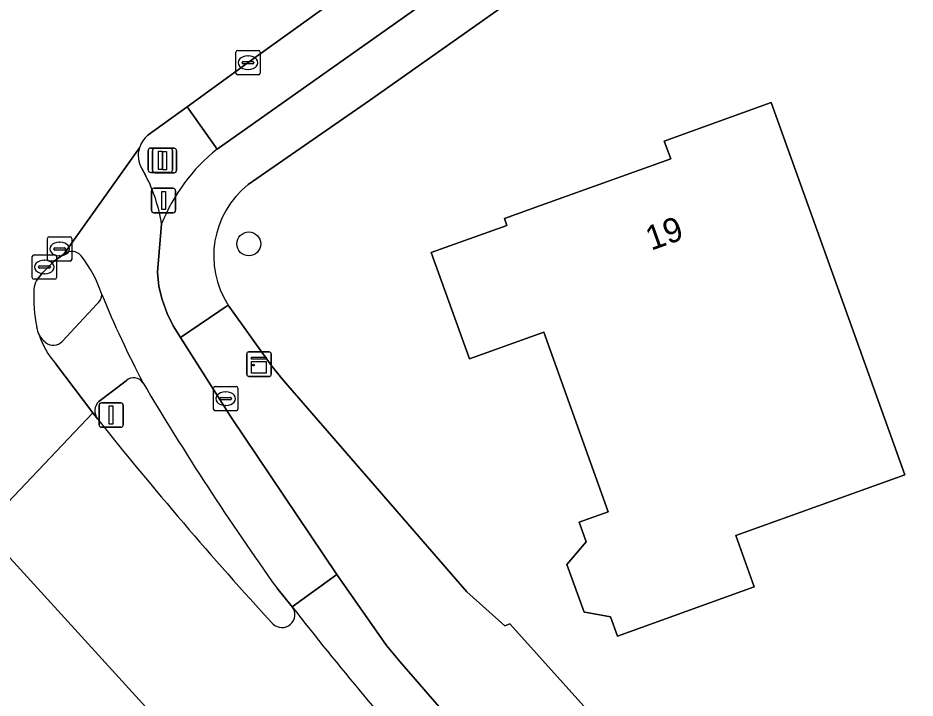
# Model space of a CAD drawing. Extents: x 161087 to 161926, y 382572 to 383873.
# Drawn here: x 161565.04 to 161601.79, y 382729.82 to 382757.68 of the extents above; entities that cross this region are included whole.
import ezdxf

# ---------------------------------------------------------------- set-up
doc = ezdxf.new("R2010")
doc.units = 0
for name, color, linetype in [('IMGEO_Berm_groen', 7, 'Continuous'), ('IMGEO_Boom', 7, 'Continuous'), ('IMGEO_Drukknoppaal', 7, 'Continuous'), ('IMGEO_Erf', 7, 'Continuous'), ('IMGEO_Fietspad_gesloten', 7, 'Continuous'), ('IMGEO_Kast', 7, 'Continuous'), ('IMGEO_Kolk', 7, 'Continuous'), ('IMGEO_Lichtmast', 7, 'Continuous'), ('IMGEO_Pand', 7, 'Continuous'), ('IMGEO_Pand_nummerreeks', 7, 'Continuous'), ('IMGEO_Rijbaan_lokaal_gesloten', 7, 'Continuous'), ('IMGEO_Rioolput', 7, 'Continuous'), ('IMGEO_Verkeerseiland_groen', 7, 'Continuous'), ('IMGEO_Verkeerseiland_open', 7, 'Continuous'), ('IMGEO_Verkeersregelinstallatiepaal', 7, 'Continuous'), ('IMGEO_Voetpad_open', 7, 'Continuous')]:
    doc.layers.add(name, color=color, linetype=linetype)

msp = doc.modelspace()

# ---------------------------------------------------------------- linework, layer by layer
at = {"layer": 'IMGEO_Berm_groen'}
msp.add_lwpolyline([(161583.108, 382762.07), (161574.467, 382755.852), (161571.968, 382754.036), (161573.199, 382752.31), (161584.417, 382760.236)], close=True, dxfattribs=at)
at = {"layer": 'IMGEO_Boom'}
msp.add_circle((161574.495, 382748.426), 0.489, dxfattribs=at)
at = {"layer": 'IMGEO_Drukknoppaal'}
for p, q in [((161570.509, 382749.804), (161570.509, 382750.604)), ((161570.509, 382750.604), (161570.509, 382749.804)), ((161570.609, 382750.704), (161571.399, 382750.704)), ((161571.399, 382750.704), (161570.609, 382750.704)), ((161571.499, 382750.604), (161571.499, 382749.804)), ((161571.499, 382749.804), (161571.499, 382750.604)), ((161571.399, 382749.704), (161570.609, 382749.704)), ((161570.609, 382749.704), (161571.399, 382749.704))]:
    msp.add_line(p, q, dxfattribs=at)
msp.add_lwpolyline([(161570.929, 382750.579), (161571.079, 382750.579), (161571.079, 382749.829), (161570.929, 382749.829), (161570.929, 382750.579)], dxfattribs=at)
for centre, start, end in [((161570.609, 382750.604), 90, 180), ((161570.609, 382750.604), 90, 180), ((161571.399, 382750.604), 0, 90), ((161571.399, 382750.604), 360, 90), ((161570.609, 382749.804), 180, 270), ((161570.609, 382749.804), 180, 270), ((161571.399, 382749.804), 270, 0), ((161571.399, 382749.804), 270, 0)]:
    msp.add_arc(centre, 0.1, start, end, dxfattribs=at)
at = {"layer": 'IMGEO_Erf'}
for points in [[(161585.099, 382758.295), (161583.93, 382757.469), (161579.443, 382754.299), (161574.477, 382750.86)], [(161573.649, 382745.916), (161575.439, 382743.417), (161575.924, 382742.835), (161583.433, 382734.169), (161584.982, 382732.778), (161585.192, 382732.858), (161589.562, 382727.999), (161609.424, 382705.975), (161609.305, 382705.895), (161625.238, 382688.024), (161643.165, 382669.38), (161647.852, 382664.262), (161649.374, 382662.6), (161650.008, 382663.023), (161699.247, 382695.877)]]:
    msp.add_lwpolyline(points, dxfattribs=at)
msp.add_lwpolyline([(161594.454, 382736.477), (161595.209, 382734.375), (161589.598, 382732.359), (161589.314, 382733.148), (161588.344, 382733.323), (161588.234, 382733.343), (161587.533, 382735.297), (161588.317, 382736.223), (161588.03, 382737.021), (161589.223, 382737.449), (161586.579, 382744.808), (161583.533, 382743.714), (161581.968, 382748.071), (161585.069, 382749.185), (161584.968, 382749.468), (161586.449, 382750), (161589.573, 382751.122), (161591.782, 382751.916), (161591.521, 382752.641), (161595.899, 382754.214), (161597.414, 382750), (161597.59, 382749.509), (161601.378, 382738.964)], close=True, dxfattribs=at)
msp.add_arc((161576.794, 382747.931), 3.735, 128.3379, 212.6472, dxfattribs=at)
at = {"layer": 'IMGEO_Fietspad_gesloten'}
for points in [[(161570.013, 382752.358), (161566.925, 382748.01)], [(161570.28, 382751.211), (161570.108, 382751.515)], [(161571.694, 382744.598), (161571.391, 382745.076), (161571.156, 382745.58), (161570.946, 382746.155), (161570.804, 382746.685), (161570.753, 382747.268), (161570.926, 382749.243)], [(161575.639, 382734.33), (161576.275, 382733.561), (161578.104, 382734.877), (161573.766, 382741.336), (161571.694, 382744.598)]]:
    msp.add_lwpolyline(points, dxfattribs=at)
for centre, radius, start, end in [((161571.032, 382752.046), 1.066, 162.985, 209.8744), ((161564.445, 382748.205), 6.564, 9.0944, 27.2506), ((161567.236, 382747.617), 0.502, 94.1565, 128.3646), ((161567.236, 382747.608), 0.511, 39.8763, 94.05), ((161563.826, 382744.884), 4.875, 17.6251, 38.7462), ((161608.75, 382762.934), 43.555, 202.3667, 207.6464), ((161673.047, 382803.798), 119.642, 210.69545, 215.49516)]:
    msp.add_arc(centre, radius, start, end, dxfattribs=at)
at = {"layer": 'IMGEO_Kast'}
for p, q in [((161574.414, 382743.075), (161574.414, 382743.916)), ((161574.414, 382743.916), (161574.414, 382743.075)), ((161574.489, 382744), (161575.33, 382744)), ((161575.33, 382744), (161574.489, 382744)), ((161575.414, 382743.925), (161575.414, 382743.084)), ((161575.414, 382743.084), (161575.414, 382743.925)), ((161575.339, 382743), (161574.498, 382743)), ((161574.498, 382743), (161575.339, 382743))]:
    msp.add_line(p, q, dxfattribs=at)
for points in [[(161574.609, 382743.79), (161575.209, 382743.79), (161575.209, 382743.705), (161574.609, 382743.705), (161574.609, 382743.79)], [(161574.609, 382743.615), (161575.209, 382743.615), (161575.209, 382743.126), (161574.609, 382743.126), (161574.609, 382743.615)]]:
    msp.add_lwpolyline(points, dxfattribs=at)
msp.add_circle((161574.693, 382743.464), 0.0377, dxfattribs=at)
for centre, start, end in [((161574.492, 382743.922), 92.4484, 184.2845), ((161574.492, 382743.922), 92.4484, 184.2845), ((161575.336, 382743.922), 2.4484, 94.2845), ((161575.336, 382743.922), 2.4484, 94.2845), ((161574.492, 382743.078), 182.4484, 274.2845), ((161574.492, 382743.078), 182.4484, 274.2845), ((161575.336, 382743.078), 272.4484, 4.2845), ((161575.336, 382743.078), 272.4484, 4.2845)]:
    msp.add_arc(centre, 0.0779, start, end, dxfattribs=at)
at = {"layer": 'IMGEO_Kolk'}
for p, q in [((161573.966, 382755.426), (161573.966, 382756.278)), ((161574.041, 382756.352), (161574.893, 382756.352)), ((161574.967, 382756.278), (161574.967, 382755.426)), ((161574.225, 382755.846), (161574.225, 382755.858)), ((161574.268, 382755.895), (161574.666, 382755.895)), ((161574.454, 382756.132), (161574.479, 382756.132)), ((161574.709, 382755.858), (161574.709, 382755.846)), ((161574.663, 382755.809), (161574.265, 382755.809)), ((161574.477, 382755.572), (161574.452, 382755.572)), ((161574.893, 382755.352), (161574.041, 382755.352)), ((161565.623, 382747.052), (161565.623, 382747.904)), ((161565.698, 382747.978), (161566.55, 382747.978)), ((161566.624, 382747.904), (161566.624, 382747.052)), ((161565.882, 382747.472), (161565.882, 382747.484)), ((161566.32, 382747.435), (161565.922, 382747.435)), ((161565.925, 382747.521), (161566.323, 382747.521)), ((161566.111, 382747.758), (161566.136, 382747.758)), ((161566.366, 382747.484), (161566.366, 382747.472)), ((161566.134, 382747.198), (161566.109, 382747.198)), ((161566.55, 382746.978), (161565.698, 382746.978)), ((161573.048, 382741.661), (161573.048, 382742.513)), ((161573.123, 382742.587), (161573.975, 382742.587)), ((161573.536, 382742.367), (161573.561, 382742.367)), ((161574.049, 382742.513), (161574.049, 382741.661)), ((161573.307, 382742.081), (161573.307, 382742.093)), ((161573.745, 382742.044), (161573.347, 382742.044)), ((161573.35, 382742.13), (161573.748, 382742.13)), ((161573.791, 382742.093), (161573.791, 382742.081)), ((161573.975, 382741.587), (161573.123, 382741.587)), ((161573.559, 382741.807), (161573.534, 382741.807))]:
    msp.add_line(p, q, dxfattribs=at)
for points in [[(161573.966, 382755.426), (161573.966, 382756.278)], [(161574.041, 382756.352), (161574.893, 382756.352)], [(161574.967, 382756.278), (161574.967, 382755.426)], [(161574.893, 382755.352), (161574.041, 382755.352)], [(161565.623, 382747.052), (161565.623, 382747.904)], [(161565.698, 382747.978), (161566.55, 382747.978)], [(161566.624, 382747.904), (161566.624, 382747.052)], [(161566.55, 382746.978), (161565.698, 382746.978)], [(161573.048, 382741.661), (161573.048, 382742.513)], [(161573.123, 382742.587), (161573.975, 382742.587)], [(161574.049, 382742.513), (161574.049, 382741.661)], [(161573.975, 382741.587), (161573.123, 382741.587)]]:
    msp.add_lwpolyline(points, dxfattribs=at)
for centre, radius, start, end in [((161574.043, 382756.276), 0.0765, 91.552, 178.448), ((161574.043, 382756.276), 0.0765, 91.552, 178.448), ((161574.891, 382756.276), 0.0765, 1.552, 88.448), ((161574.891, 382756.276), 0.0765, 1.552, 88.448), ((161574.265, 382755.855), 0.0403, 85.8775, 175.7526), ((161574.67, 382755.857), 0.0386, 1.7309, 96.639), ((161574.262, 382755.845), 0.0366, 178.938, 274.7102), ((161574.666, 382755.852), 0.043, 264.8664, 352.4533), ((161574.043, 382755.428), 0.0765, 181.552, 268.448), ((161574.043, 382755.428), 0.0765, 181.552, 268.448), ((161574.891, 382755.428), 0.0765, 271.552, 358.448), ((161574.891, 382755.428), 0.0765, 271.552, 358.448), ((161565.7, 382747.902), 0.0765, 91.552, 178.448), ((161565.7, 382747.902), 0.0765, 91.552, 178.448), ((161566.548, 382747.902), 0.0765, 1.552, 88.448), ((161566.548, 382747.902), 0.0765, 1.552, 88.448), ((161565.922, 382747.481), 0.0403, 85.8775, 175.7526), ((161565.919, 382747.471), 0.0366, 178.938, 274.7102), ((161566.323, 382747.478), 0.043, 264.8664, 352.4533), ((161566.327, 382747.483), 0.0386, 1.7309, 96.639), ((161565.7, 382747.054), 0.0765, 181.552, 268.448), ((161565.7, 382747.054), 0.0765, 181.552, 268.448), ((161566.548, 382747.054), 0.0765, 271.552, 358.448), ((161566.548, 382747.054), 0.0765, 271.552, 358.448), ((161573.125, 382742.511), 0.0765, 91.552, 178.448), ((161573.125, 382742.511), 0.0765, 91.552, 178.448), ((161573.973, 382742.511), 0.0765, 1.552, 88.448), ((161573.973, 382742.511), 0.0765, 1.552, 88.448), ((161573.347, 382742.09), 0.0403, 85.8775, 175.7526), ((161573.344, 382742.08), 0.0366, 178.938, 274.7102), ((161573.748, 382742.087), 0.043, 264.8664, 352.4533), ((161573.752, 382742.092), 0.0386, 1.7309, 96.639), ((161573.125, 382741.663), 0.0765, 181.552, 268.448), ((161573.125, 382741.663), 0.0765, 181.552, 268.448), ((161573.973, 382741.663), 0.0765, 271.552, 358.448), ((161573.973, 382741.663), 0.0765, 271.552, 358.448)]:
    msp.add_arc(centre, radius, start, end, dxfattribs=at)
for centre, major_axis, ratio, start_param, end_param in [((161574.453, 382755.852), (-0.387, 0.002), 0.722429, 4.712389, 7.853982), ((161574.478, 382755.852), (-0.39, 0.002), 0.717154, 1.570796, 4.712389), ((161566.11, 382747.478), (-0.387, 0.002), 0.722429, 4.712389, 7.853982), ((161566.135, 382747.478), (-0.39, 0.002), 0.717154, 1.570796, 4.712389), ((161573.535, 382742.087), (-0.387, 0.002), 0.722429, 4.712389, 7.853982), ((161573.56, 382742.087), (-0.39, 0.002), 0.717154, 1.570796, 4.712389)]:
    msp.add_ellipse(centre, major_axis=major_axis, ratio=ratio, start_param=start_param, end_param=end_param, dxfattribs=at)
at = {"layer": 'IMGEO_Lichtmast'}
for p, q in [((161570.376, 382751.454), (161570.376, 382752.254)), ((161570.376, 382752.254), (161570.376, 382751.454)), ((161570.476, 382752.354), (161571.266, 382752.354)), ((161571.266, 382752.354), (161570.476, 382752.354)), ((161571.366, 382752.254), (161571.366, 382751.454)), ((161571.366, 382751.454), (161571.366, 382752.254)), ((161571.266, 382751.354), (161570.476, 382751.354)), ((161570.476, 382751.354), (161571.266, 382751.354)), ((161568.462, 382741.914), (161569.252, 382741.914)), ((161569.252, 382741.914), (161568.462, 382741.914)), ((161568.362, 382741.014), (161568.362, 382741.814)), ((161568.362, 382741.814), (161568.362, 382741.014)), ((161569.352, 382741.814), (161569.352, 382741.014)), ((161569.352, 382741.014), (161569.352, 382741.814)), ((161569.252, 382740.914), (161568.462, 382740.914)), ((161568.462, 382740.914), (161569.252, 382740.914))]:
    msp.add_line(p, q, dxfattribs=at)
for points in [[(161570.796, 382752.229), (161570.946, 382752.229), (161570.946, 382751.479), (161570.796, 382751.479), (161570.796, 382752.229)], [(161568.782, 382741.789), (161568.932, 382741.789), (161568.932, 382741.039), (161568.782, 382741.039), (161568.782, 382741.789)]]:
    msp.add_lwpolyline(points, dxfattribs=at)
for centre, start, end in [((161570.476, 382752.254), 90, 180), ((161570.476, 382752.254), 90, 180), ((161571.266, 382752.254), 0, 90), ((161571.266, 382752.254), 360, 90), ((161570.476, 382751.454), 180, 270), ((161570.476, 382751.454), 180, 270), ((161571.266, 382751.454), 270, 0), ((161571.266, 382751.454), 270, 0), ((161568.462, 382741.814), 90, 180), ((161568.462, 382741.814), 90, 180), ((161569.252, 382741.814), 0, 90), ((161569.252, 382741.814), 360, 90), ((161568.462, 382741.014), 180, 270), ((161568.462, 382741.014), 180, 270), ((161569.252, 382741.014), 270, 0), ((161569.252, 382741.014), 270, 0)]:
    msp.add_arc(centre, 0.1, start, end, dxfattribs=at)
at = {"layer": 'IMGEO_Pand'}
msp.add_lwpolyline([(161597.59, 382749.509), (161597.414, 382750), (161595.899, 382754.214), (161591.521, 382752.641), (161591.782, 382751.916), (161589.573, 382751.122), (161586.449, 382750), (161584.968, 382749.468), (161585.069, 382749.185), (161581.968, 382748.071), (161583.533, 382743.714), (161586.579, 382744.808), (161589.223, 382737.449), (161588.03, 382737.021), (161588.317, 382736.223), (161587.533, 382735.297), (161588.234, 382733.343), (161588.344, 382733.323), (161589.314, 382733.148), (161589.598, 382732.359), (161595.209, 382734.375), (161594.454, 382736.477), (161601.378, 382738.964)], close=True, dxfattribs=at)
at = {"layer": 'IMGEO_Rijbaan_lokaal_gesloten'}
for points in [[(161570.366, 382752.877), (161571.968, 382754.036), (161574.467, 382755.852), (161583.108, 382762.07), (161586.012, 382764.231), (161587.661, 382765.339)], [(161565.793, 382746.923), (161566.041, 382747.244), (161566.525, 382747.721), (161566.925, 382748.01), (161570.013, 382752.358)], [(161563.602, 382736.77), (161568.108, 382741.507), (161566.572, 382743.531)], [(161568.297, 382741.258), (161568.108, 382741.507), (161563.602, 382736.77)], [(161563.602, 382736.77), (161592.087, 382705.487), (161622.627, 382671.947), (161661.586, 382630.771), (161701.238, 382588.176), (161728.827, 382571.874), (161779.525, 382578.285), (161779.123, 382582.55), (161766.2, 382581.371), (161761.033, 382580.909)], [(161645.804, 382661.238), (161642.351, 382664.758), (161637.265, 382669.796), (161627.567, 382679.823), (161618.288, 382689.808), (161609.858, 382699.184), (161593.448, 382717.185), (161584.083, 382727.396), (161580.691, 382731.313), (161580.138, 382731.973), (161578.104, 382734.877), (161576.275, 382733.561)]]:
    msp.add_lwpolyline(points, dxfattribs=at)
for centre, radius, start, end in [((161571.026, 382752.049), 1.059, 128.5419, 163.0146), ((161566.711, 382746.478), 1.02, 154.1292, 174.7554), ((161571.424, 382746.189), 5.741, 176.1829, 191.8685), ((161566.749, 382745.15), 0.955, 188.5306, 208.2284), ((161569.149, 382745.77), 3.414, 198.2975, 220.9806), ((161690.519, 382838.569), 156.229, 218.52637, 222.58178), ((161575.853, 382733.24), 0.53, 226.1289, 37.2011), ((161683.305, 382816.893), 135.645, 217.90373, 221.83054), ((161683.305, 382816.893), 135.645, 217.90373, 221.83054)]:
    msp.add_arc(centre, radius, start, end, dxfattribs=at)
at = {"layer": 'IMGEO_Rioolput'}
for p, q in [((161566.245, 382747.793), (161566.245, 382748.645)), ((161566.32, 382748.719), (161567.172, 382748.719)), ((161567.246, 382748.645), (161567.246, 382747.793)), ((161566.504, 382748.213), (161566.504, 382748.225)), ((161566.942, 382748.176), (161566.544, 382748.176)), ((161566.547, 382748.262), (161566.945, 382748.262)), ((161566.733, 382748.499), (161566.758, 382748.499)), ((161566.988, 382748.225), (161566.988, 382748.213)), ((161566.756, 382747.939), (161566.731, 382747.939)), ((161567.172, 382747.719), (161566.32, 382747.719))]:
    msp.add_line(p, q, dxfattribs=at)
for points in [[(161566.245, 382747.793), (161566.245, 382748.645)], [(161566.32, 382748.719), (161567.172, 382748.719)], [(161567.246, 382748.645), (161567.246, 382747.793)], [(161567.172, 382747.719), (161566.32, 382747.719)]]:
    msp.add_lwpolyline(points, dxfattribs=at)
for centre, radius, start, end in [((161566.322, 382748.643), 0.0765, 91.552, 178.448), ((161566.322, 382748.643), 0.0765, 91.552, 178.448), ((161567.17, 382748.643), 0.0765, 1.552, 88.448), ((161567.17, 382748.643), 0.0765, 1.552, 88.448), ((161566.544, 382748.222), 0.0403, 85.8775, 175.7526), ((161566.541, 382748.212), 0.0366, 178.938, 274.7102), ((161566.945, 382748.219), 0.043, 264.8664, 352.4533), ((161566.949, 382748.224), 0.0386, 1.7309, 96.639), ((161566.322, 382747.795), 0.0765, 181.552, 268.448), ((161566.322, 382747.795), 0.0765, 181.552, 268.448), ((161567.17, 382747.795), 0.0765, 271.552, 358.448), ((161567.17, 382747.795), 0.0765, 271.552, 358.448)]:
    msp.add_arc(centre, radius, start, end, dxfattribs=at)
for centre, major_axis, ratio, start_param, end_param in [((161566.732, 382748.219), (-0.387, 0.002), 0.722429, 4.712389, 7.853982), ((161566.757, 382748.219), (-0.39, 0.002), 0.717154, 1.570796, 4.712389)]:
    msp.add_ellipse(centre, major_axis=major_axis, ratio=ratio, start_param=start_param, end_param=end_param, dxfattribs=at)
at = {"layer": 'IMGEO_Verkeerseiland_groen'}
for points in [[(161569.476, 382742.819), (161568.351, 382741.975)], [(161576.275, 382733.561), (161575.639, 382734.33)]]:
    msp.add_lwpolyline(points, dxfattribs=at)
for centre, radius, start, end in [((161569.784, 382742.497), 0.446, 30.6274, 133.7389), ((161673.047, 382803.798), 119.642, 210.69545, 215.49516), ((161568.741, 382741.585), 0.551, 134.9919, 216.3941), ((161690.519, 382838.569), 156.229, 218.52637, 222.58178), ((161575.853, 382733.24), 0.53, 226.1289, 37.2011)]:
    msp.add_arc(centre, radius, start, end, dxfattribs=at)
at = {"layer": 'IMGEO_Verkeerseiland_open'}
for points in [[(161566.925, 382748.01), (161566.525, 382747.721), (161566.041, 382747.244), (161565.793, 382746.923)], [(161566.855, 382744.432), (161568.273, 382745.958)]]:
    msp.add_lwpolyline(points, dxfattribs=at)
for centre, radius, start, end in [((161567.236, 382747.617), 0.502, 94.1565, 128.3646), ((161567.236, 382747.608), 0.511, 39.8763, 94.05), ((161563.826, 382744.884), 4.875, 17.6251, 38.7462), ((161566.711, 382746.478), 1.02, 154.1292, 174.7554), ((161571.424, 382746.189), 5.741, 176.1829, 191.8685), ((161567.964, 382746.361), 0.508, 307.4727, 359.8542), ((161566.749, 382745.15), 0.955, 188.5306, 208.2284), ((161566.766, 382745.155), 0.972, 208.052, 232.4861), ((161566.488, 382744.78), 0.506, 231.5767, 316.4869)]:
    msp.add_arc(centre, radius, start, end, dxfattribs=at)
at = {"layer": 'IMGEO_Verkeersregelinstallatiepaal'}
for p, q in [((161570.548, 382751.442), (161570.548, 382752.242)), ((161570.548, 382752.242), (161570.548, 382751.442)), ((161570.648, 382752.342), (161571.438, 382752.342)), ((161571.438, 382752.342), (161570.648, 382752.342)), ((161571.538, 382752.242), (161571.538, 382751.442)), ((161571.538, 382751.442), (161571.538, 382752.242)), ((161571.438, 382751.342), (161570.648, 382751.342)), ((161570.648, 382751.342), (161571.438, 382751.342))]:
    msp.add_line(p, q, dxfattribs=at)
msp.add_lwpolyline([(161570.968, 382752.217), (161571.118, 382752.217), (161571.118, 382751.467), (161570.968, 382751.467), (161570.968, 382752.217)], dxfattribs=at)
for centre, start, end in [((161570.648, 382752.242), 90, 180), ((161570.648, 382752.242), 90, 180), ((161571.438, 382752.242), 0, 90), ((161571.438, 382752.242), 360, 90), ((161570.648, 382751.442), 180, 270), ((161570.648, 382751.442), 180, 270), ((161571.438, 382751.442), 270, 0), ((161571.438, 382751.442), 270, 0)]:
    msp.add_arc(centre, 0.1, start, end, dxfattribs=at)
at = {"layer": 'IMGEO_Voetpad_open'}
for points in [[(161574.477, 382750.86), (161579.443, 382754.299), (161583.93, 382757.469), (161585.099, 382758.295), (161585.017, 382758.404), (161586.678, 382759.589), (161588.667, 382761.008), (161590.565, 382762.379), (161595.594, 382766.012), (161595.696, 382765.813), (161596.009, 382765.952), (161595.848, 382766.199), (161596.018, 382766.327), (161596.158, 382766.372), (161601.023, 382767.942), (161624.636, 382775.599), (161633.162, 382778.456), (161637.427, 382779.982), (161667.594, 382789.929), (161673.242, 382791.575), (161679.143, 382793.516), (161684.809, 382795.379)], [(161593.521, 382768.958), (161594.389, 382767.317), (161587.392, 382762.338), (161586.012, 382764.231), (161583.108, 382762.07), (161584.417, 382760.236), (161573.199, 382752.31)], [(161571.968, 382754.036), (161570.366, 382752.877)], [(161573.199, 382752.31), (161571.968, 382754.036)], [(161570.108, 382751.515), (161570.28, 382751.211)], [(161570.926, 382749.243), (161570.753, 382747.268), (161570.804, 382746.685), (161570.946, 382746.155), (161571.156, 382745.58), (161571.391, 382745.076), (161571.694, 382744.598), (161573.649, 382745.916)], [(161568.273, 382745.958), (161566.855, 382744.432)], [(161585.192, 382732.858), (161584.982, 382732.778), (161583.433, 382734.169), (161575.924, 382742.835), (161575.439, 382743.417), (161573.649, 382745.916), (161571.694, 382744.598), (161573.766, 382741.336), (161578.104, 382734.877), (161580.138, 382731.973), (161580.691, 382731.313), (161584.083, 382727.396), (161593.448, 382717.185), (161609.858, 382699.184), (161618.288, 382689.808), (161627.567, 382679.823), (161637.265, 382669.796), (161642.351, 382664.758), (161645.804, 382661.238)], [(161566.572, 382743.531), (161568.108, 382741.507), (161568.297, 382741.258)], [(161568.351, 382741.975), (161569.476, 382742.819)], [(161651.703, 382659.86), (161649.374, 382662.6), (161647.852, 382664.262), (161643.165, 382669.38), (161625.238, 382688.024), (161609.305, 382705.895), (161609.424, 382705.975), (161589.562, 382727.999), (161585.192, 382732.858)]]:
    msp.add_lwpolyline(points, dxfattribs=at)
for centre, radius, start, end in [((161571.026, 382752.049), 1.059, 128.5419, 163.0146), ((161571.032, 382752.046), 1.066, 162.985, 209.8744), ((161577.836, 382746.497), 7.436, 128.5835, 158.3311), ((161577.836, 382746.497), 7.436, 128.5835, 158.3311), ((161564.445, 382748.205), 6.564, 9.0944, 27.2506), ((161576.794, 382747.931), 3.735, 128.3379, 212.6472), ((161567.964, 382746.361), 0.508, 307.4727, 359.8542), ((161608.75, 382762.934), 43.555, 202.3667, 207.6464), ((161566.766, 382745.155), 0.972, 208.052, 232.4861), ((161569.149, 382745.77), 3.414, 198.2975, 220.9806), ((161566.488, 382744.78), 0.506, 231.5767, 316.4869), ((161569.784, 382742.497), 0.446, 30.6274, 133.7389), ((161568.741, 382741.585), 0.551, 134.9919, 216.3941)]:
    msp.add_arc(centre, radius, start, end, dxfattribs=at)

# ---------------------------------------------------------------- texts
at = {"layer": 'IMGEO_Pand_nummerreeks'}
msp.add_text('19', height=1, rotation=19.7616, dxfattribs=at).set_placement((161590.98, 382748.143))

doc.saveas('drawing.dxf')
